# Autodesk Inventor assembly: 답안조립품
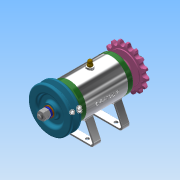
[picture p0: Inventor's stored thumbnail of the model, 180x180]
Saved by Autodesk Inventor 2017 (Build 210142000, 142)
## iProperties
Part Number: 답안조립품
Material: 일반
Document SubType Name: Assembly
Designer: Administrator
Author: Administrator
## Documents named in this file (16)
- C:\Users\Administrator\Desktop\711206V1002\답안조립품.iam
- C:\Users\Administrator\Desktop\711206V1002\본체.ipt
- C:\Users\Administrator\Desktop\711206V1002\711206V1002\V벨트풀리.ipt
- C:\Users\Administrator\Desktop\711206V1002\711206V1002\너트 M8.ipt
- C:\Users\Administrator\Desktop\711206V1002\711206V1002\니플 M6 x 0.75.ipt
- C:\Users\Administrator\Desktop\711206V1002\711206V1002\베어링 6002.ipt
- C:\Users\Administrator\Desktop\711206V1002\711206V1002\볼트 M4 x 12.ipt
- C:\Users\Administrator\Desktop\711206V1002\711206V1002\볼트 M6 x 8.ipt
- C:\Users\Administrator\Desktop\711206V1002\711206V1002\스프로킷.ipt
- C:\Users\Administrator\Desktop\711206V1002\711206V1002\스프링와셔 8.ipt
- C:\Users\Administrator\Desktop\711206V1002\711206V1002\오일 실 15 x 25 x 7.ipt
- C:\Users\Administrator\Desktop\711206V1002\711206V1002\와셔 6 x 11.5.ipt
- C:\Users\Administrator\Desktop\711206V1002\711206V1002\와셔 8 x 17.ipt
- C:\Users\Administrator\Desktop\711206V1002\711206V1002\축.ipt
- C:\Users\Administrator\Desktop\711206V1002\711206V1002\커버.ipt
- C:\Users\Administrator\Desktop\711206V1002\711206V1002\키 3 x 3.ipt
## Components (11 placed, 3 different names)
1. V벨트풀리:1
2. KS B 2023 6002 - 15 x 32 x 9:1
3. KS B 2023 6002 - 15 x 32 x 9:2
4. ISO 4762 M4 x 12:2 — 각도:3
5. ISO 4762 M4 x 12:3
6. ISO 4762 M4 x 12:4
7. ISO 4762 M4 x 12:5
8. ISO 4762 M4 x 12:1 — 각도:2
9. ISO 4762 M4 x 12:6
10. ISO 4762 M4 x 12:7
11. ISO 4762 M4 x 12:8
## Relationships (2: Angle 2)
- 각도:2 [Angle]: ISO 4762 M4 x 12:1
- 각도:3 [Angle]: ISO 4762 M4 x 12:2
